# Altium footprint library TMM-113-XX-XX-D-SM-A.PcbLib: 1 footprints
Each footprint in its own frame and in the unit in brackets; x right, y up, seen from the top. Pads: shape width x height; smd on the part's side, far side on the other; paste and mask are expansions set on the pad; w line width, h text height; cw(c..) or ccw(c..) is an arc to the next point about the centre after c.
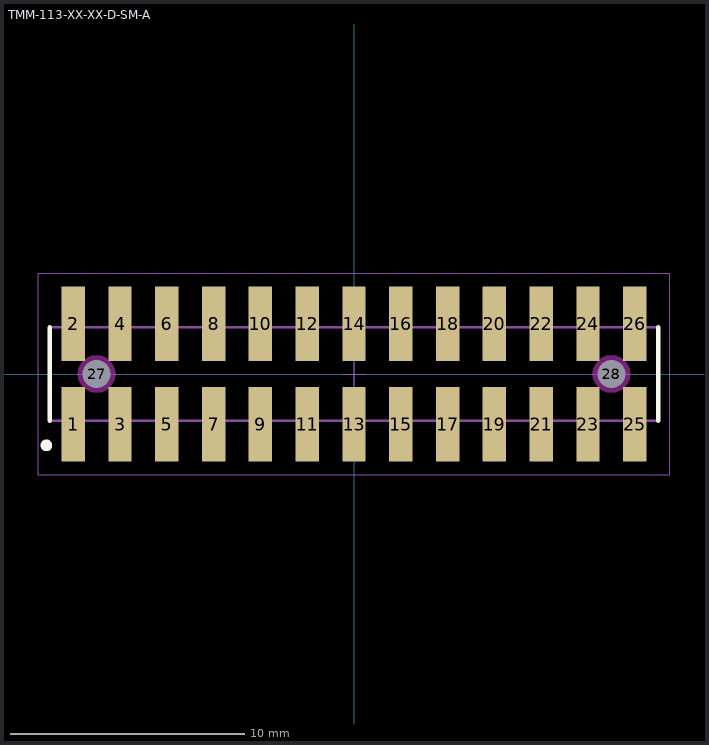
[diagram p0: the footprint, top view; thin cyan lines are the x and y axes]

## TMM-113-XX-XX-D-SM-A [mm] "2.00mm pitch, 26 pin, terminal strip; double row, w/alignment pins, SMT"
height 2.77
pads (28):
  rect 1x3.2 smd mask+0: 1(-12,-2.15) 2(-12,2.15) 3(-10,-2.15) 4(-10,2.15) 5(-8,-2.15) 6(-8,2.15) 7(-6,-2.15) 8(-6,2.15) 9(-4,-2.15) 10(-4,2.15) 11(-2,-2.15) 12(-2,2.15) 13(0,-2.15) 14(0,2.15) 15(2,-2.15) 16(2,2.15) 17(4,-2.15) 18(4,2.15) 19(6,-2.15) 20(6,2.15) 21(8,-2.15) 22(8,2.15) 23(10,-2.15) 24(10,2.15) 25(12,-2.15) 26(12,2.15)
  round 1 hole 1.2 unplated mask+0: 27(-11,0) 28(11,0)
Top Overlay:
  circle w0.25: c-13.15,-3.05 r0.125
  lines w0.2: -13,-2 -13,2 ; 13,-2 13,2
Keep-Out Layer:
  pour cut-out: 11.807,0 11.779,0.209 11.699,0.403 11.571,0.571 11.403,0.699 11.209,0.779 11,0.807 10.791,0.779 10.597,0.699 10.429,0.571 10.301,0.403 10.221,0.209 10.193,0 10.221,-0.209 10.301,-0.403 10.429,-0.571 10.597,-0.699 10.791,-0.779 11,-0.807 11.209,-0.779 11.403,-0.699 11.571,-0.571 11.699,-0.403 11.779,-0.209
  pour cut-out: -10.193,0 -10.221,0.209 -10.301,0.403 -10.429,0.571 -10.597,0.699 -10.791,0.779 -11,0.807 -11.209,0.779 -11.403,0.699 -11.571,0.571 -11.699,0.403 -11.779,0.209 -11.807,0 -11.779,-0.209 -11.699,-0.403 -11.571,-0.571 -11.403,-0.699 -11.209,-0.779 -11,-0.807 -10.791,-0.779 -10.597,-0.699 -10.429,-0.571 -10.301,-0.403 -10.221,-0.209
Mechanical 12:
  lines w0.001: -13,-2 -13,2 13,2 13,-2 -13,-2
Mechanical 13:
  lines w0.1: -13,-2 -13,2 ; -13,-2 13,-2 ; -13,-2 -13,2 ; -13,2 13,2 ; 13,-2 13,2 ; 13,-2 13,2
  text ".Designator" at 0,-0.127 h1.52
Mechanical 15:
  lines w0.05: -0.5,0 0.5,0 ; 0,-0.5 0,0.5 ; -13.5,-4.3 -13.5,4.3 13.5,4.3 13.5,-4.3 -13.5,-4.3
